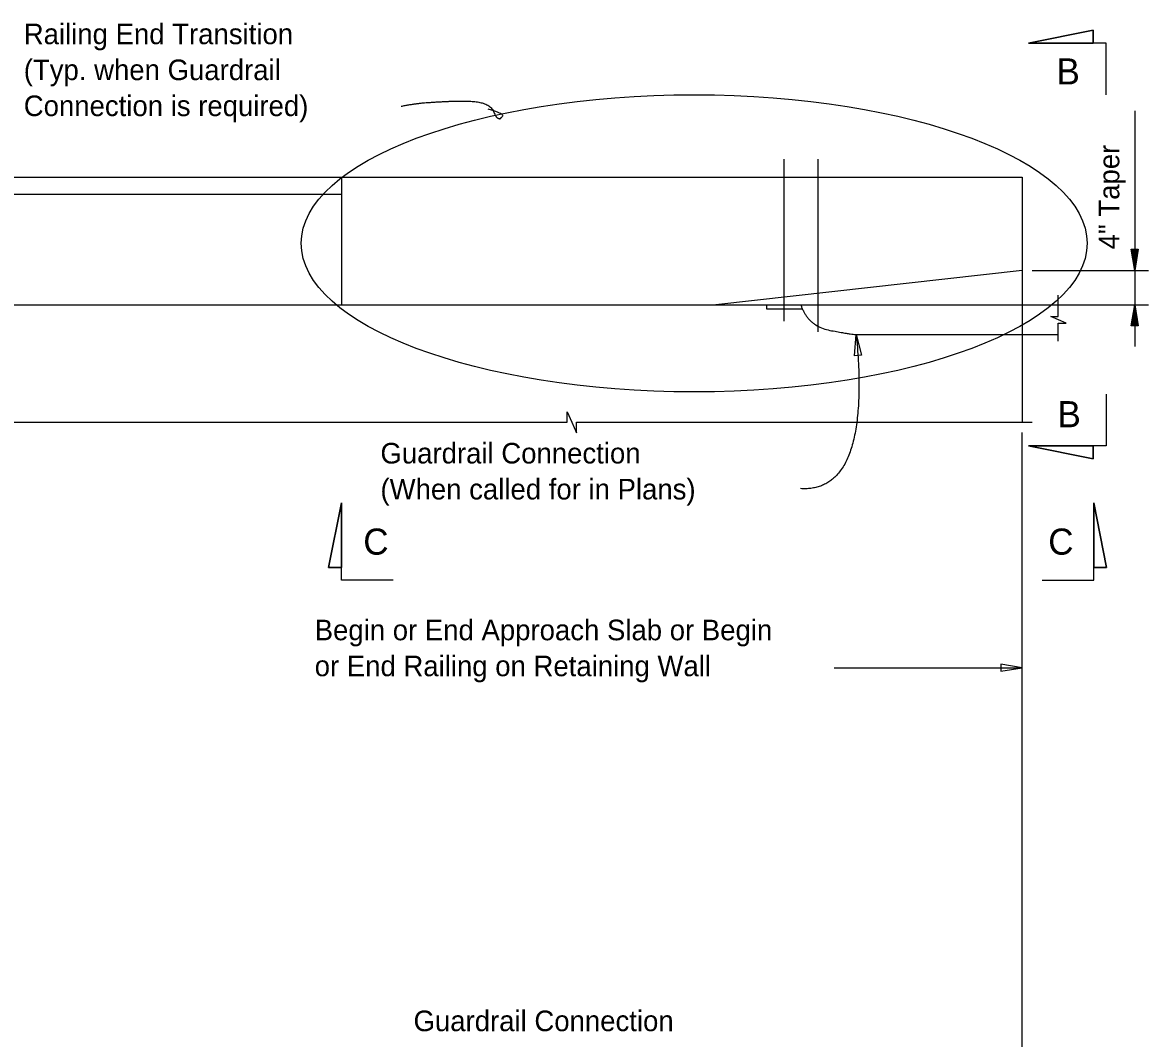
# Model space of a CAD drawing. Extents: x 0 to 40.8, y 1 to 28.
# Drawn here: x 29.77 to 40.79, y 15.78 to 25.73 of the extents above; entities that cross this region are included whole.
import ezdxf

# ---------------------------------------------------------------- set-up
doc = ezdxf.new("R2010")
doc.units = 0
for name, color, linetype in [('Dimension', 7, 'Continuous'), ('Miscellaneous', 7, 'Continuous'), ('TextStructures', 7, 'Continuous'), ('TrafBarrierConc', 7, 'Continuous')]:
    doc.layers.add(name, color=color, linetype=linetype)

# ---------------------------------------------------------------- blocks, each defined once
blk = doc.blocks.new('ALT')
at = {"layer": 'Dimension'}
for points in [[(0, 0), (-0.000633, -0.000105), (-0.000633, 0.000105)], [(-0.00018, 0), (-0.000604, -0.000069), (-0.000604, 0.000072)], [(-0.000361, 0), (-0.000574, -0.000036), (-0.000574, 0.000036)]]:
    blk.add_lwpolyline(points, close=True, dxfattribs=at)

msp = doc.modelspace()

# ---------------------------------------------------------------- linework, layer by layer
at = {"layer": 'Dimension'}
for p, q in [((39.621, 25.523), (40.254, 25.649)), ((40.254, 25.649), (40.254, 25.523)), ((40.38, 25.523), (39.621, 25.523)), ((40.38, 25.017), (40.38, 25.523)), ((40.66, 24.86), (40.66, 22.552)), ((37.223, 24.387), (37.223, 22.801)), ((37.556, 24.387), (37.556, 22.695)), ((39.657, 23.296), (40.795, 23.296)), ((39.657, 22.962), (40.795, 22.962)), ((40.38, 22.086), (40.38, 21.58)), ((39.557, 20.999), (39.557, 21.71)), ((39.557, 14.076), (39.557, 21.71)), ((40.38, 21.58), (39.621, 21.58)), ((39.621, 21.58), (40.254, 21.454)), ((40.254, 21.454), (40.254, 21.58)), ((32.89, 21.023), (32.763, 20.39)), ((32.89, 20.264), (32.89, 21.023)), ((40.258, 20.264), (40.258, 21.023)), ((40.258, 21.023), (40.385, 20.39)), ((32.763, 20.39), (32.89, 20.39)), ((40.385, 20.39), (40.258, 20.39)), ((33.396, 20.264), (32.89, 20.264)), ((39.752, 20.264), (40.258, 20.264)), ((37.717, 19.407), (39.557, 19.407))]:
    msp.add_line(p, q, dxfattribs=at)
for points in [[(40.254, 25.523), (40.254, 25.649), (39.621, 25.523)], [(37.914, 22.461), (37.933, 22.671), (37.985, 22.467)], [(40.254, 21.58), (40.254, 21.454), (39.621, 21.58)], [(32.89, 20.39), (32.763, 20.39), (32.89, 21.023)], [(40.258, 20.39), (40.385, 20.39), (40.258, 21.023)], [(39.557, 19.407), (39.348, 19.443), (39.348, 19.372)]]:
    msp.add_lwpolyline(points, close=True, dxfattribs=at)
for points in [[(39.91, 22.606), (39.91, 22.78), (39.988, 22.78), (39.838, 22.847), (39.91, 22.847), (39.91, 23.054)], [(23.475, 21.811), (24.368, 21.811), (24.368, 21.914), (24.413, 21.811), (24.458, 21.707), (24.458, 21.811), (30.348, 21.811)], [(34.608, 21.811), (35.103, 21.811), (35.103, 21.914), (35.148, 21.811), (35.193, 21.707), (35.193, 21.811), (39.657, 21.811)], [(30.348, 21.811), (34.608, 21.811)]]:
    msp.add_lwpolyline(points, dxfattribs=at)
for points in [[(33.477, 24.906), (33.624, 24.935), (33.86, 24.95), (34.029, 24.957), (34.236, 24.953), (34.363, 24.901), (34.404, 24.795), (34.443, 24.782), (34.443, 24.782), (34.494, 24.83), (34.327, 24.876)], [(37.933, 22.671), (38.081, 21.117), (37.387, 21.161)]]:
    msp.add_open_spline(points, degree=2, dxfattribs=at)
at = {"layer": 'Miscellaneous'}
for p, q in [((37.056, 22.962), (39.91, 22.962)), ((37.056, 22.917), (37.056, 22.962)), ((37.399, 22.917), (37.056, 22.917)), ((37.933, 22.671), (39.91, 22.671))]:
    msp.add_line(p, q, dxfattribs=at)
msp.add_open_spline([(37.389, 22.962), (37.459, 22.751), (37.899, 22.669), (37.933, 22.671)], degree=2, dxfattribs=at)
at = {"layer": 'TextStructures'}
msp.add_ellipse((36.345, 23.563), major_axis=(-3.848, 0), ratio=0.378139, dxfattribs=at)
at = {"layer": 'TrafBarrierConc'}
for p, q in [((23.575, 24.212), (39.557, 24.212)), ((32.89, 24.212), (32.89, 22.962)), ((39.557, 24.212), (39.557, 21.811)), ((23.575, 24.046), (32.89, 24.046)), ((39.557, 23.296), (36.557, 22.962)), ((23.575, 22.962), (39.557, 22.962))]:
    msp.add_line(p, q, dxfattribs=at)

# ---------------------------------------------------------------- block references
at = {"layer": 'Dimension', "xscale": 329.26230569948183, "yscale": 333.375}
for p, rotation in [((40.66, 23.296), -90), ((40.66, 22.962), 90)]:
    msp.add_blockref('ALT', p, dxfattribs=dict(at, rotation=rotation))

# ---------------------------------------------------------------- texts
at = {"layer": 'Dimension'}
for s, p in [('Begin or End Approach Slab or Begin ', (32.629, 19.676)), ('or End Railing on Retaining Wall', (32.629, 19.324)), ('Guardrail Connection', (33.597, 15.848))]:
    msp.add_text(s, height=0.2016, dxfattribs=at).set_placement(p)
at = {"layer": 'TextStructures'}
for s, height, p in [('Railing End Transition', 0.2016, (29.78, 25.513)), ('(Typ. when Guardrail', 0.2016, (29.78, 25.161)), ('B', 0.256, (39.894, 25.119)), ('Connection is required)', 0.2016, (29.78, 24.809)), ('B', 0.256, (39.904, 21.762)), ('Guardrail Connection', 0.2016, (33.273, 21.407)), ('(When called for in Plans)', 0.2016, (33.273, 21.055)), ('C', 0.256, (33.105, 20.514)), ('C', 0.256, (39.813, 20.514))]:
    msp.add_text(s, height=height, dxfattribs=at).set_placement(p)
msp.add_text('4" Taper', height=0.2016, rotation=90, dxfattribs=at).set_placement((40.509, 23.504))

doc.saveas('drawing.dxf')
